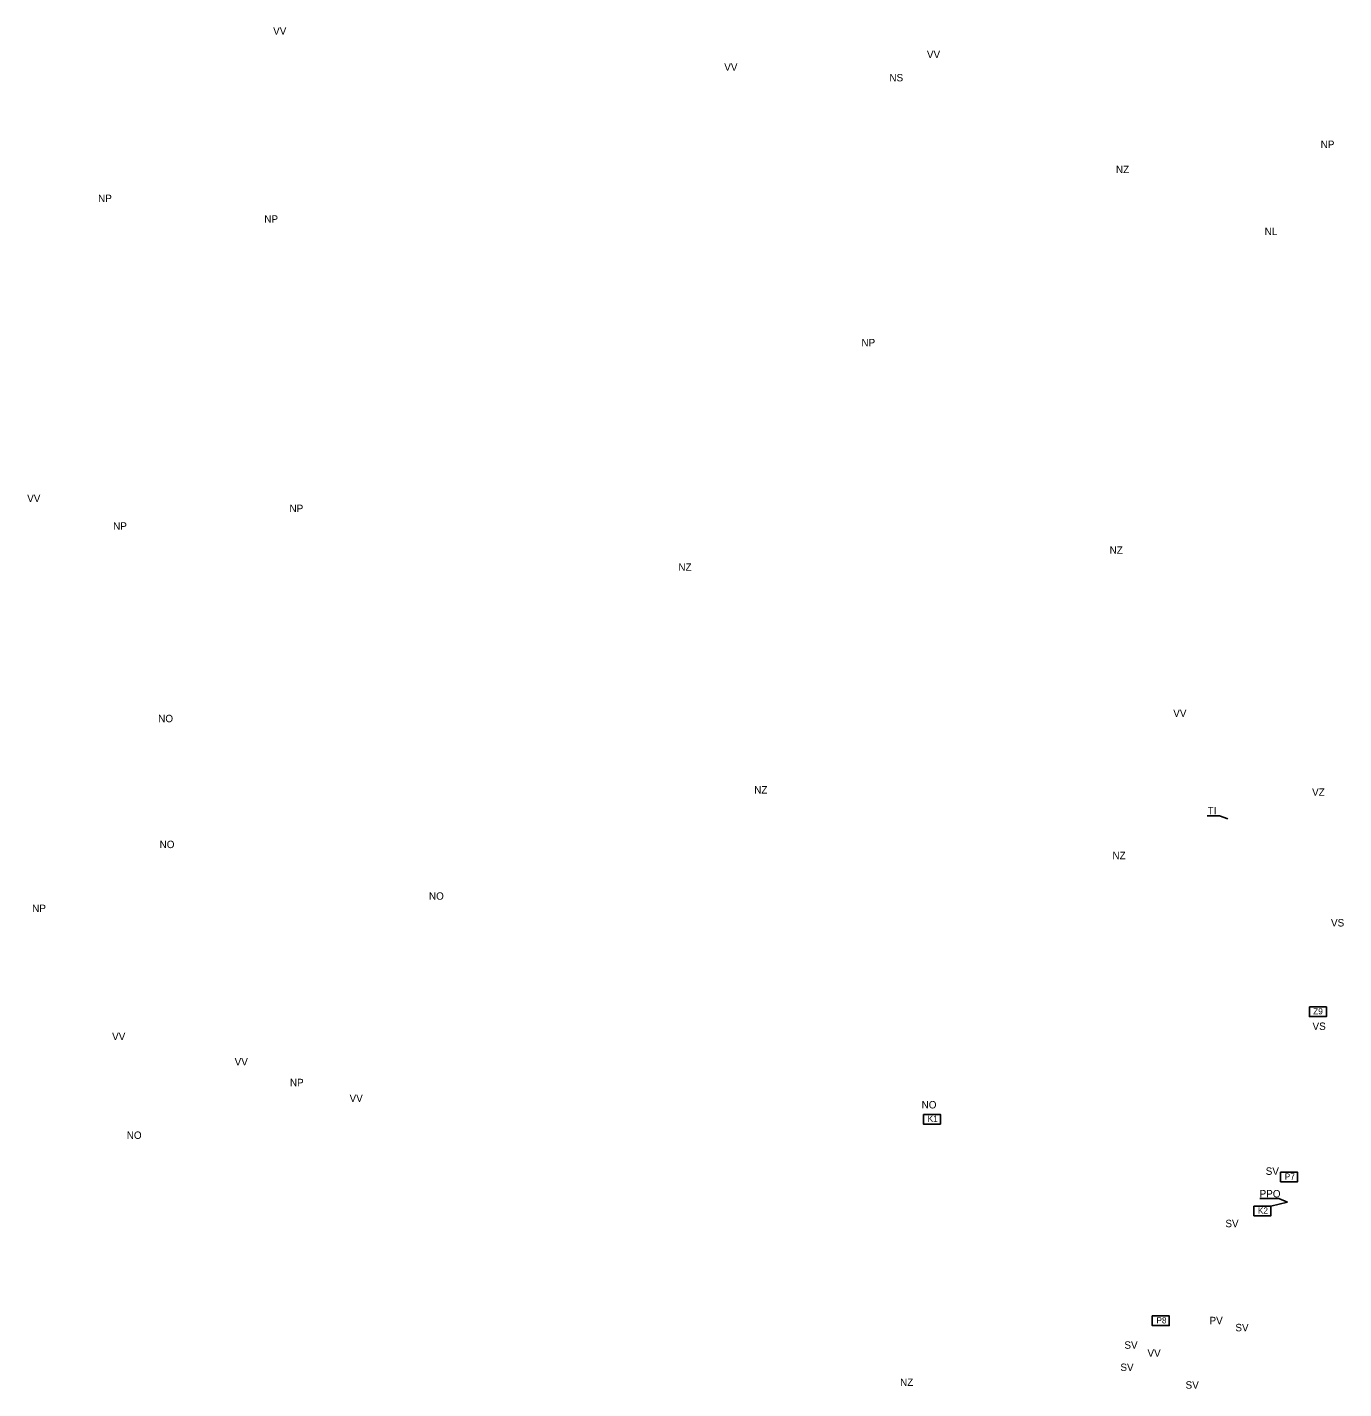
# Model space of a CAD drawing. Extents: x -546576 to -528254, y -1046225 to -1035772.
# Drawn here: x -544896 to -542765, y -1040309 to -1038105 of the extents above; entities that cross this region are included whole.
import ezdxf

# ---------------------------------------------------------------- set-up
doc = ezdxf.new("R2010")
doc.units = 0
for name, color, linetype in [('Vrstva 10', 7, 'Continuous'), ('Vrstva 11', 7, 'Continuous'), ('Vrstva 3', 7, 'Continuous'), ('Vrstva 4', 7, 'Continuous'), ('Vrstva 7', 7, 'Continuous')]:
    doc.layers.add(name, color=color, linetype=linetype)

msp = doc.modelspace()

# ---------------------------------------------------------------- linework, layer by layer
at = {"layer": 'Vrstva 10'}
msp.add_lwpolyline([(-542986.2, -1039381.4), (-542966, -1039381.4), (-542952.4, -1039386.3)], dxfattribs=at)
at = {"layer": 'Vrstva 11'}
msp.add_lwpolyline([(-542900.9, -1040000.9), (-542870, -1040000.9), (-542855.9, -1040007)], dxfattribs=at)
at = {"layer": 'Vrstva 3'}
msp.add_lwpolyline([(-542820.6, -1039690.7), (-542820.6, -1039706.3), (-542793.1, -1039706.3), (-542793.1, -1039690.7), (-542820.6, -1039690.7)], dxfattribs=at)
at = {"layer": 'Vrstva 4'}
for points in [[(-542867.3, -1039958.3), (-542867.3, -1039973.8), (-542839.8, -1039973.8), (-542839.8, -1039958.3), (-542867.3, -1039958.3)], [(-543075, -1040191.1), (-543075, -1040206.6), (-543047.5, -1040206.6), (-543047.5, -1040191.1), (-543075, -1040191.1)]]:
    msp.add_lwpolyline(points, dxfattribs=at)
at = {"layer": 'Vrstva 7'}
msp.add_line((-542882.8, -1040013.4), (-542855.9, -1040007), dxfattribs=at)
for points in [[(-543445.4, -1039864.8), (-543445.4, -1039880.3), (-543417.9, -1039880.3), (-543417.9, -1039864.8), (-543445.4, -1039864.8)], [(-542910.3, -1040013.4), (-542910.3, -1040028.9), (-542882.8, -1040028.9), (-542882.8, -1040013.4), (-542910.3, -1040013.4)]]:
    msp.add_lwpolyline(points, dxfattribs=at)

# ---------------------------------------------------------------- texts
at = {"layer": 'Vrstva 10'}
for s, p in [('VV', (-544498.3, -1038116.6)), ('VV', (-543439.8, -1038154.5)), ('VV', (-543767.9, -1038175.1)), ('NS', (-543500.6, -1038192.2)), ('NP', (-542802.3, -1038300.2)), ('NZ', (-543133.7, -1038340.8)), ('NP', (-544781.7, -1038387.6)), ('NP', (-544512.6, -1038421.1)), ('NL', (-542893, -1038441.2)), ('NP', (-543545.9, -1038621.1)), ('VV', (-544896.5, -1038873.3)), ('NP', (-544471.8, -1038889.6)), ('NP', (-544757.3, -1038918.2)), ('NZ', (-543144, -1038957.1)), ('NZ', (-543842.2, -1038984.6)), ('VV', (-543041, -1039221.2)), ('NO', (-544684.4, -1039229.8)), ('NZ', (-543719.4, -1039345.2)), ('VZ', (-542816.2, -1039348.9)), ('TI', (-542985.3, -1039378.9)), ('NO', (-544682.1, -1039433.6)), ('NZ', (-543139.4, -1039451.6)), ('NO', (-544246, -1039517.2)), ('NP', (-544888.4, -1039537.1)), ('VS', (-542785.6, -1039560.5)), ('VV', (-544759, -1039744.5)), ('VV', (-544560.6, -1039785.5)), ('NP', (-544471.1, -1039819.1)), ('VV', (-544374.5, -1039844.6)), ('NO', (-544735.3, -1039904.4)), ('SV', (-542956.6, -1040047.4)), ('SV', (-542956.6, -1040047.4)), ('PV', (-542982.3, -1040204.5)), ('SV', (-542940.4, -1040215.9)), ('VV', (-543082.7, -1040257.2)), ('SV', (-543126.6, -1040280.2)), ('NZ', (-543483.3, -1040304.4))]:
    msp.add_text(s, height=12, dxfattribs=at).set_placement(p)
at = {"layer": 'Vrstva 11'}
for s, p in [('VS', (-542815.5, -1039728)), ('NO', (-543448.4, -1039855.1)), ('SV', (-542891.3, -1039962.6)), ('PPO', (-542901.2, -1039999.2)), ('SV', (-543120.1, -1040244.2)), ('SV', (-543021, -1040308.8))]:
    msp.add_text(s, height=12, dxfattribs=at).set_placement(p)
at = {"layer": 'Vrstva 3'}
msp.add_text('Z9', height=10, dxfattribs=at).set_placement((-542814.4, -1039702.8))
at = {"layer": 'Vrstva 4'}
for s, p in [('P7', (-542860.4, -1039970.4)), ('P8', (-543068.2, -1040203.2))]:
    msp.add_text(s, height=10, dxfattribs=at).set_placement(p)
at = {"layer": 'Vrstva 7'}
for s, p in [('K1', (-543438.7, -1039876.8)), ('K2', (-542904, -1040025.4))]:
    msp.add_text(s, height=10, dxfattribs=at).set_placement(p)

doc.saveas('drawing.dxf')
